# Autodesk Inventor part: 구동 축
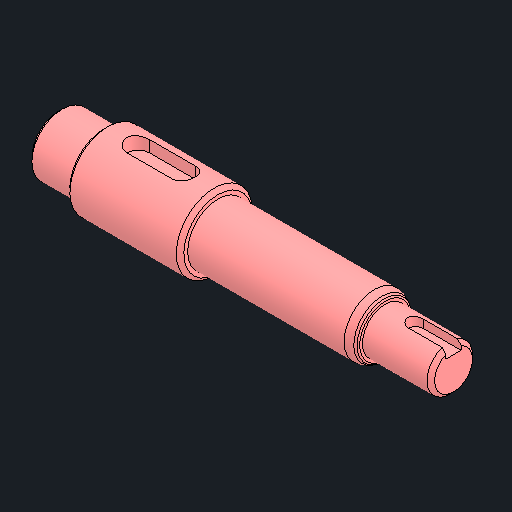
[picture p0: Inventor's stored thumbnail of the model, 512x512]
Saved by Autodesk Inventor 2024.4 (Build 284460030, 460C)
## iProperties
Created: 2026-09
Part Number: 구동 축
Material: 강철, 탄소
Document SubType Name: Modeling
Designer: user
Density: 7.85 g/cm^3
Appearance: 기본값
Author: jhkim
Sending System: Autodesk Inventor 2027
Preprocessor: ST-DEVELOPER v20.1
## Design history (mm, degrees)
feature "솔리드1"
node "솔리드2"
